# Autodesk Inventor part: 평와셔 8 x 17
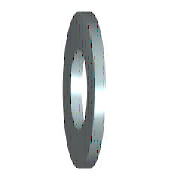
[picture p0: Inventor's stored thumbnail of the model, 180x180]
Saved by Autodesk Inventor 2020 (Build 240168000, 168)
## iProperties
Created: 2012-02
Part Number: 평와셔 8 x 17
Material: 강철, 연강
Description: 평면 와셔
Document SubType Name: Modeling
Standard: KS B 1326
Designer: mduedu
Standards Organization: KS
Language: ko-KR
Size Designation: 8x17
Categories: <MemberInstance><Categories><Category DisplayName="조임쇠" InternalName="e4da775c-781d-43d5-af7c-5136215cf5a6" Mnemonic="FSTN"><Category DisplayName="와셔" InternalN
Density: 1 g/cm^3
Appearance: 주황색
IsCustomPart: 1
Author: mduedu
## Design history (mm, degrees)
sketch "스케치"
  geometry: C1 r 8.5 at (0, 0); C2 r 4.2 at (0, 0); 1 further point
  constraints: 2 centre point, 2 coincident
  dimensions: "d0" = 8.4 diameter of C2 (= SD1); "d1" = 17 diameter of C1 (= SD2)
extrude "본체" new body sketch "스케치" distance "d2" = 1.6 (= SD); taper "d3" = 0 deg
workaxis "Work Axis1"
workplane "Work Plane1"
body "Solid1"
other parameters: "SD1" = 8.4 [user parameter; used in 1 equation term], "SD2" = 17 [user parameter; used in 1 equation term], "SD" = 1.6 [user parameter; used in 1 equation term], "d4" = 0, "d5" = 0, "d6" = 0, "d7" = 0, "NND" = 8 [user parameter]
